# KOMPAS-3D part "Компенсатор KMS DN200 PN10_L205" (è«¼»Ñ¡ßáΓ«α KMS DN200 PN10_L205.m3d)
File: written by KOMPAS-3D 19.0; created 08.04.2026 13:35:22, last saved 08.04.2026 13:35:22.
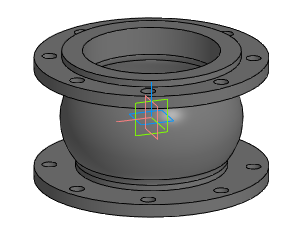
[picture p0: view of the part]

Document properties: Автор: Энергия; Полное имя файла: Z:\3.Личные\kachalov\3d для проектировщиков\7.1 Компенсатор\stp_Компенсатор KSM\Компенсатор KMS DN200 PN10_L205.m3d

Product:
- Part/product: Компенсатор KMS DN200 PN10_L205

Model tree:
1. Операция без истории:1  (labels: Компенсатор KMS DN200 PN10_L205)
